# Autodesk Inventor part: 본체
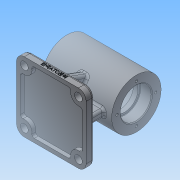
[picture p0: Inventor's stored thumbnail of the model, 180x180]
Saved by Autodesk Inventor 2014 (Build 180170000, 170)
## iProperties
Created: 2019-06
Part Number: 본체
Material: 일반
Document SubType Name: Modeling
Designer: net
Density: 1 g/cm^3
Appearance: 기본값
Author: net
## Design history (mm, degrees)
sketch "스케치1"
  geometry: L1 (-45, 0)-(45, 0); L2 (45, 0)-(45, 32); L3 (45, 32)-(-45, 32); L4 (-45, 32)-(-45, 0); 2 further points
  constraints: 8 end point, 2 parallel, 1 coincident, 1 horizontal, 1 midpoint, 1 perpendicular
  dimensions: "d0" = 90 distance of L2.end L3.end; "d1" = 64 diameter of L3 L1
revolve "회전1" sketch "스케치1" stored, may be unused: angle "d2" = 90 deg
node "작업 평면1"
sketch "스케치2"
  geometry: L1 (-45, 45)-(45, 45); L2 (45, 45)-(45, -45); L3 (45, -45)-(-45, -45); L4 (-45, -45)-(-45, 45); L5 (-45, 45)-(45, -45); L6 (45, 45)-(-45, -45); 1 further point
  constraints: 12 end point, 2 midpoint, 2 parallel, 1 horizontal, 1 perpendicular
  dimensions: "d4" = 90 distance of L1.start L1.end; "d5" = 90 distance of L1.end L2.end
extrude "돌출1" join sketch "스케치2" distance "d6" = 10; taper "d7" = 0 deg
sketch "스케치3"
  geometry: L1 (0, 5)-(-55, 5); L2 (-55, 5)-(-55, -5); L3 (-55, -5)-(0, -5); L4 (0, -5)-(0, 5); L5 (-65, 45)-(-65, -45) reference; L6 (-65, 45)-(-55, 45) reference; L7 (-55, -45)-(-55, 45) reference; L8 (-65, -45)-(-55, -45) reference; C1 r 32 at (0, 0) reference; 2 further points
  constraints: 8 end point, 3 midpoint, 2 parallel, 1 horizontal, 1 horizontal alignment, 1 perpendicular
  dimensions: "d8" = 10 distance of L3.end L1.start
extrude "돌출2" join sketch "스케치3" stored distance "d9" = 70; taper "d10" = 0 deg
sketch "스케치4"
  geometry: L1 (-55, -45)-(-55, 45) reference; L2 (-55, 5)-(-31.607, 5) reference; L3 (-31.607, -5)-(-55, -5) reference; L4 (-55, 35)-(-20, 22.261); L5 (-20, 22.261)-(-20, -22.261); L6 (-20, -22.261)-(-55, -35); L7 (-55, 35)-(-55, -35); 2 further points
  constraints: 8 end point, 2 point on line, 1 collinear, 1 equal length, 1 horizontal alignment, 1 midpoint, 1 perpendicular
  dimensions: "d11" = 10 distance of L4.start L1.end; "d12" = 110 deg angle of L4 L1; "d13" = 35 distance between parallel lines of L1 L5
extrude "돌출3" join sketch "스케치4" stored distance "d14" = 10; taper "d15" = 0 deg
sketch "스케치5"
  geometry: L1 (-45, -32)-(-45, 32) reference; L2 (-45, 32)-(45, 32) reference; L3 (45, -32)-(45, 32) reference; L4 (-45, 0)-(45, 0); L5 (-45, 20)-(-30, 20); L6 (-30, 20)-(-30, 17); L7 (-30, 17)-(-24, 17); L8 (-24, 17)-(-24, 25); L9 (-24, 25)-(24, 25); L10 (24, 25)-(24, 17); L11 (24, 17)-(30, 17); L12 (30, 17)-(30, 20); L13 (30, 20)-(45, 20); L14 (45, 20)-(45, 0); L15 (-45, 20)-(-45, 0); 1 further point
  constraints: 24 end point, 7 parallel, 3 collinear, 3 equal length, 2 midpoint, 2 perpendicular, 2 point on line
  dimensions: "d16" = 15 distance of L5.start L5.end; "d17" = 48 distance of L8.end L9.end; "d18" = 50 diameter of L9 L4; "d19" = 40 diameter of L5 L4; "d20" = 34 diameter of L7 L4
revolve "회전2" sketch "스케치5" stored, may be unused: angle "d21" = 90 deg
node "작업 평면2"
sketch "스케치6"
  geometry: C1 r 5 at (0, 0); 1 further point
  constraints: 1 centre point, 1 coincident
  dimensions: "d23" = 10 diameter of C1
extrude "돌출4" join sketch "스케치6" distance "d24" = 10; taper "d25" = 0 deg
hole "구멍1" diameter "d28" = 4.917; stored, may be unused: countersink angle "d32" = 90 deg, drill point angle "d34" = 118 deg; dims "d29" = 6, "d30" = 4, "d31" = 2, "d33" = 12, "d35" = 10, "d36" = 10
hole "구멍2" diameter "d39" = 10; stored, may be unused: countersink angle "d43" = 90 deg, drill point angle "d45" = 0 deg; dims "d37" = 10, "d38" = 10, "d40" = 6, "d41" = 4, "d42" = 2, "d44" = 10
fillet "모깎기1" dims "d52" = 10
sketch "스케치7"
  geometry: L1 (-40, 40)-(-26.34, 40); L2 (40, 40)-(40, 26.34); L3 (40, -40)-(26.34, -40); L4 (-40, -40)-(-40, -26.34); L5 (-40, 40)-(40, -40); L6 (40, 40)-(-40, -40); L7 (-26.34, 40)-(26.34, 40); L8 (-40, 26.34)-(-40, 40); L9 (26.34, 40)-(40, 40); L10 (40, -26.34)-(40, -40); L11 (26.34, -40)-(-26.34, -40); L12 (-26.34, -40)-(-40, -40); L13 (-40, -26.34)-(-40, 26.34); L14 (40, 26.34)-(40, -26.34); C1 r 5 at (-35, 35) reference; C2 r 5 at (35, 35) reference; C3 r 5 at (-35, -35) reference; C4 r 5 at (35, -35) reference; A1 r 10 centre (-35, 35) between (-26.34, 40) and (-40, 26.34); A2 r 10 centre (35, 35) between (40, 26.34) and (27.929, 27.929); A3 r 10 centre (35, -35) between (40, -26.34) and (26.34, -40); A4 r 10 centre (-35, -35) between (-26.34, -40) and (-40, -26.34); A5 r 10 centre (35, 35) between (27.929, 27.929) and (40, 26.34); 1 further point
  constraints: 28 end point, 18 parallel, 11 point on circle, 9 perpendicular, 5 centre point, 4 coincident, 3 horizontal, 2 midpoint, 1 point on line
  dimensions: "d53" = 80 distance of L1.start L2.start; "d54" = 80 distance of L2.start L3.start; "d55" = 20 diameter of A1; "d56" = 20 diameter of A2; "d57" = 20 diameter of A3; "d58" = 20 diameter of A4
extrude "돌출5" cut sketch "스케치7" distance "d59" = 5; taper "d60" = 0 deg
fillet "모깎기2" dims "d61" = 3
fillet "모깎기3" dims "d62" = 3
fillet "모깎기4" dims "d63" = 3
fillet "모깎기5" dims "d64" = 3
fillet "모깎기6" dims "d65" = 2
chamfer "모따기1" distance "d66" = 1; stored, may be unused: second distance "d67" = 2, angle "d68" = 45 deg
fillet "모깎기7" dims "d69" = 3
fillet "모깎기8" dims "d70" = 0.6
sketch "스케치8"
  geometry: C1 r 32 at (0, 0) reference; 1 further point
  constraints: 1 vertical alignment
  dimensions: "d71" = 25 distance of C1.centre point (0, 25)
hole "구멍3" sketch "스케치8" at (0, 25) diameter "d72" = 3.242; stored, may be unused: countersink angle "d76" = 90 deg, drill point angle "d78" = 118 deg; dims "d73" = 7, "d74" = 4, "d75" = 2, "d77" = 9
sketch "스케치9"
  geometry: L1 (70, 0)-(0, 0) reference; L2 (-10, 7)-(-10, 0) reference; 2 further points
  constraints: 1 other
  dimensions: "d82" = 4 distance from line of point (35, 4) L1; "d83" = 45 distance from line of point (35, 4) L2
feature "엠보싱1" sketch "스케치9" dims "d84" = 0.5, "d85" = 0
node "솔리드1"
pattern_linear "직사각형 패턴1" dims "d48" = 70
pattern_circular "원형 패턴1" dims angle "d80" = 360 deg
mirror "대칭1"
node "투영된 루프1"
other parameters: "d3" = -65
